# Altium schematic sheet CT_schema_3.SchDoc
size 279 x 211 mm
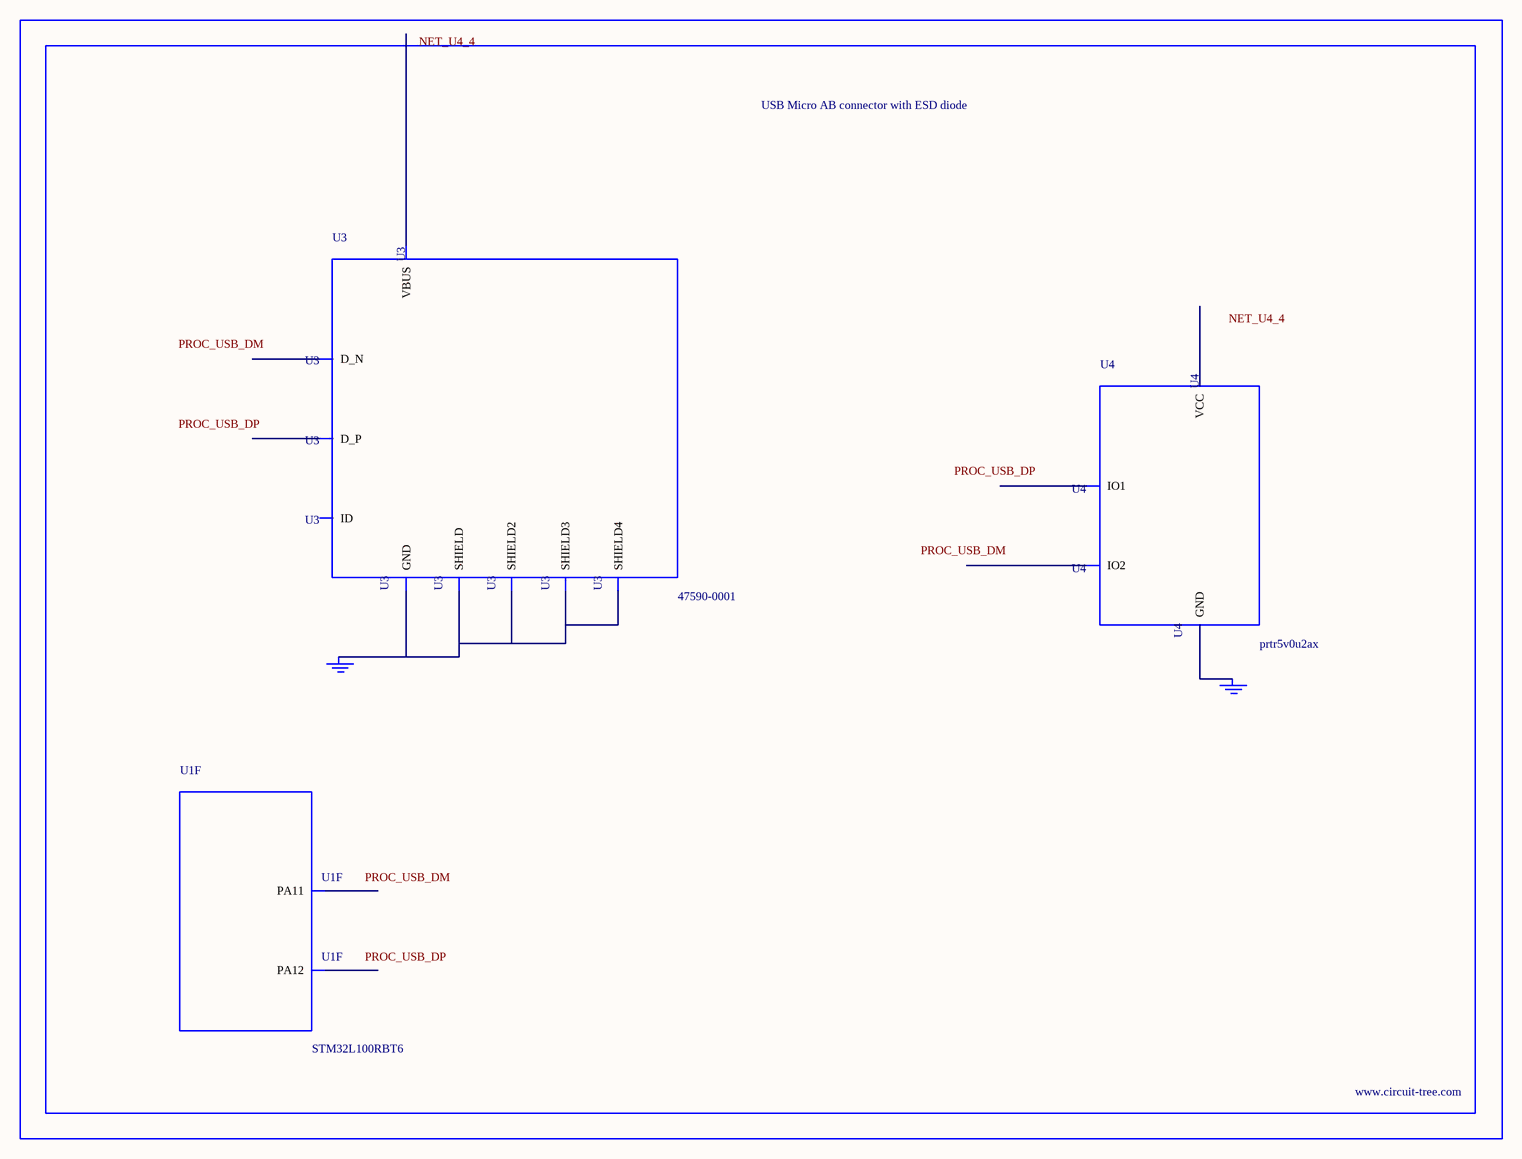
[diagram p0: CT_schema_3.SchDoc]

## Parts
BORDER2  (no value)
GND_INSTANCE_2_0  (no value)
GND_INSTANCE_2_1  (no value)
U1  STM32L100RBT6  [LQFP64]  (part F of 7)
U3  47590-0001  [MICRO_USB_AB]
U4  prtr5v0u2ax  [SOT143B]

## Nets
NetGND_INSTANCE_2_0_0: GND_INSTANCE_2_0.0(GND) U3.5(GND) U3.6(SHIELD) U3.7(SHIELD2) U3.8(SHIELD3) U3.9(SHIELD4)
NetGND_INSTANCE_2_1_0: GND_INSTANCE_2_1.0(GND) U4.1(GND)

Not connected (* = marked no-connect by the designer): U1 44(PA11) 45(PA12); U3 1(VBUS) 2(D_N) 3(D_P) 4(ID); U4 2(IO1) 3(IO2) 4(VCC)

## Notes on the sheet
- Labels drawn without touching a wire or pin: NET_U4_4, PROC_USB_DM, PROC_USB_DP

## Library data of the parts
BORDER2 = BORDER_PAGE2
GND_INSTANCE_2_0 GND_INSTANCE_2_1 = GND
